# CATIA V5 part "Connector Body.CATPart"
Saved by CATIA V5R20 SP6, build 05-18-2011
Part number: Connector Body
Bounding box of the stored display mesh (mm): x -10 to 10, y -56.99 to 0, z 0 to 7
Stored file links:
  E:\#01 CATIA Lecture Materials\#06 DMU\#03 DMU Page01 KIN EX03\Connector Body.CATPart
  C:\Program Files\Dassault Systemes\B20\win_b64\reffiles\standard\MetricThickPitch.txt
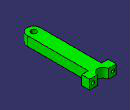
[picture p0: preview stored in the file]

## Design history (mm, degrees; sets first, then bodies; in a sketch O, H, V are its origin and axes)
Set1 "Reference Data"
  Point1 "Center Point": (0, 0, 0)
Body1 (main body)
  Body2
    Sketch1 on xy-plane, origin (0, 0, 0), H (0, 1, 0), V (-1, 0, 0)
      arc A1 centre (0, 0) radius 4 from (0, 4) to (0, -4) ccw
      circle A2 centre (-52, 0) radius 2
      point P1 (-52, 0)
      point P2 (0, 4)
      line L1 (0, 4) -> (0, 10)
      point P3 (0, 10)
      line L2 (0, 10) -> (-6, 10)
      point P4 (-6, 10)
      line L3 (-6, 10) -> (-6, 5)
      point P5 (-6, 5)
      line L4 (-6, 5) -> (-52, 5)
      point P6 (-6, -5)
      point P7 (-6, -10)
      point P8 (0, -10)
      line L5 (-6, -5) -> (-52, -5)
      line L6 (-6, -10) -> (-6, -5)
      line L7 (0, -10) -> (-6, -10)
      line L8 (0, -4) -> (0, -10)
      arc A3 centre (-52, 0) radius 5 from (-52, 5) to (-52, -5) ccw
      distance L2 L7 = 20
      radius A1 = 4
      radius A2 = 2
      distance L4 L5 = 10
      distance P1 V = 52
      distance L8 L6 = 6
      coincidence: P1 H, P2 A1, P2 V, P2 L1
      vertical: L1 V, L3 V
      horizontal: L2 H, L4 H
      symmetry: P5 P6 H, P4 P7 H, P3 P8 H, L4 L5 H, L3 L6 H, L2 L7 H, L1 L8 H
      tangency: A3 L4
    Pad1: profile Sketch1, direction (0, 0, 1), length 7
    Sketch2 on face of Pad1 from Sketch1.L1, origin (-7.2626, 0, 3.8064), H (1, 0, 0), V (0, 0, -1)
      point P1 (-0.2374, 0.3064)
      reference intersected line E1 through (7.2626, 0) direction (0, 1) from yz-plane
      reference intersected line E2 through (0, 3.8064) direction (1, 0) from xy-plane
      distance P1 E1 = 7.5
      distance P1 E2 = 3.5
    Hole1: placed by Sketch2, at (-7.5, 0, 3.5) direction (0, -1, 0), diameter 2.459, depth 10, threaded "M3", thread diameter 3, thread depth 10, pitch 0.5
    Mirror1: of Hole1, about yz-plane
  Assemble1: tool Body2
